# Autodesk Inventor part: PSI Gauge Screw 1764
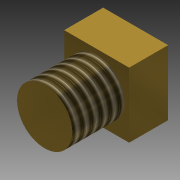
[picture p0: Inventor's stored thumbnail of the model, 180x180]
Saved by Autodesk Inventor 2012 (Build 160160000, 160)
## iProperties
Created: 2010-02
Part Number: PSI Gauge Screw 1764
Document SubType Name: Modeling
Designer: jgehrig
Density: 1 g/cm^3
Material: Default
Author: jgehrig
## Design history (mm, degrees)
sketch "Sketch1"
  geometry: L1 (-10.386, 10.749)-(2.314, 10.749); L2 (2.314, 10.749)-(2.314, -1.951); L3 (2.314, -1.951)-(-10.386, -1.951); L4 (-10.386, -1.951)-(-10.386, 10.749); 1 further point
  constraints: 8 end point, 2 parallel, 1 horizontal, 1 perpendicular
  dimensions: "d0" = 12.7 distance of L1.start L1.end; "d1" = 12.7 distance of L3.end L1.start
extrude "Extrusion1" new body sketch "Sketch1" distance "d2" = 7.62; taper "d3" = 0 deg
sketch "Sketch2"
  geometry: C1 r 5.397 at (-4.036, 4.399); 1 further point
  constraints: 1 centre point
  dimensions: "d4" = 10.795 diameter of C1
extrude "Extrusion2" join sketch "Sketch2" distance "d5" = 10.16; taper "d6" = 0 deg
thread "Thread1" dims "d7" = 25.4, "d8" = 0
body "Solid1"
